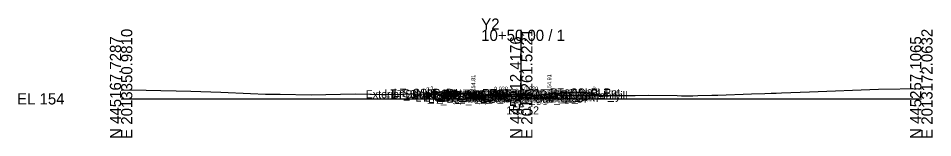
# Model space of a CAD drawing. Extents: x -26 to 203, y -10 to 6017.
# Drawn here: x -25.7 to 202.8, y 990.3 to 1020.1 of the extents above; entities that cross this region are included whole.
import ezdxf

# ---------------------------------------------------------------- set-up
doc = ezdxf.new("R2010")
doc.units = 0
for name, color, linetype in [('Default', 7, 'Continuous'), ('Exist CMT Pavement', 7, 'Continuous'), ('Exist Cross Section Cell', 7, 'Continuous'), ('Exist XS Center Line Elevation Label', 7, 'Continuous'), ('Exist XS Ground Line', 7, 'Continuous'), ('Prop CMT Conc Surface', 7, 'Continuous'), ('Prop CMT Concrete Structures', 7, 'Continuous'), ('Prop CMT Pvmt Course 1', 7, 'Continuous'), ('Prop CMT Pvmt Course 1 CG', 7, 'Continuous'), ('Prop CMT Pvmt Course 2', 7, 'Continuous'), ('Prop CMT Pvmt Course 3', 7, 'Continuous'), ('Prop CMT Pvmt Surface', 7, 'Continuous'), ('Prop CMT Pvmt Wedge Surface 1', 7, 'Continuous'), ('Prop CMT Pvmt Wedge Surface 2', 7, 'Continuous'), ('Prop CMT Pvmt Wedge Surface 3', 7, 'Continuous'), ('Prop CMT Slope Grass', 7, 'Continuous'), ('Prop CMT Subgrade Earthwork', 7, 'Continuous'), ('Prop XS Earthwork Shape', 7, 'Continuous'), ('Prop XS Hydro Elevations', 7, 'Continuous'), ('Prop XS SE Text', 7, 'Continuous'), ('Prop XS Side Slope Text', 7, 'Continuous'), ('Scratch_Level_0', 7, 'Continuous')]:
    doc.layers.add(name, color=color, linetype=linetype)

msp = doc.modelspace()

# ---------------------------------------------------------------- linework, layer by layer
at = {"layer": 'Exist CMT Pavement'}
for points in [[(100, 1001.12), (99.62, 1001.13), (91.64, 1000.99), (91, 1000.98)], [(100, 1001.12), (105, 1001.01)]]:
    msp.add_lwpolyline(points, dxfattribs=at)
at = {"layer": 'Exist Cross Section Cell'}
for p, q in [((100, 1000), (100, 1017.25)), ((0, 1000), (100, 1000)), ((100, 1000), (200, 1000))]:
    msp.add_line(p, q, dxfattribs=at)
at = {"layer": 'Exist XS Ground Line'}
msp.add_lwpolyline([(0, 1002.19), (2.58, 1002.21), (9.96, 1002.11), (13.76, 1002), (17.41, 1001.91), (24.94, 1001.69), (32.32, 1001.34), (36.12, 1001.15), (39.78, 1001.13), (47.51, 1001.03), (58.48, 1001.23), (62.14, 1001.2), (69.66, 1001.12), (70.75, 1001.13), (86.79, 1001.22), (87.86, 1001.19), (89.46, 1000.95), (91.64, 1000.99), (99.62, 1001.13), (100, 1001.12), (106.61, 1000.97), (112.21, 1000.87), (113.83, 1000.85), (118.7, 1000.83), (128.51, 1000.86), (131.77, 1000.91), (139, 1000.8), (140.03, 1000.79), (142.9, 1000.78), (144.16, 1000.81), (147.67, 1000.93), (149.16, 1000.95), (157.51, 1001.24), (160.88, 1001.33), (162.43, 1001.4), (162.94, 1001.43), (163.69, 1001.45), (165.06, 1001.5), (172.01, 1001.76), (189.29, 1002.45), (200, 1002.61)], dxfattribs=at)
at = {"layer": 'Prop CMT Conc Surface'}
for points in [[(88, 1000.81), (88, 1001.31), (87.5, 1001.31)], [(105, 1001.03), (107, 1000.91)], [(107, 1000.91), (107, 1001.41), (107.5, 1001.41)], [(90, 1000.93), (88, 1000.81)]]:
    msp.add_lwpolyline(points, dxfattribs=at)
at = {"layer": 'Prop CMT Concrete Structures'}
for points in [[(90, 1000.93), (88, 1000.81), (88, 1001.31), (87.5, 1001.31)], [(87.5, 1001.31), (87.5, 1000.3), (90, 1000.35)], [(105, 1001.03), (107, 1000.91), (107, 1001.41), (107.5, 1001.41)], [(107.5, 1001.41), (107.5, 1000.4), (105, 1000.45)], [(105, 1000.45), (105, 1001.03)], [(90, 1000.35), (90, 1000.93)]]:
    msp.add_lwpolyline(points, dxfattribs=at)
at = {"layer": 'Prop CMT Pvmt Course 1'}
for points in [[(100, 1001.13), (90, 1000.93)], [(91, 1000.83), (100, 1001.01)], [(100, 1000.88), (100, 1001.13)], [(100, 1001.13), (105, 1001.03)], [(100, 1000.88), (100, 1001.13)], [(100, 1001.01), (100, 1000.88), (100, 1000.88)], [(105, 1000.91), (100, 1001.01)], [(100, 1001.01), (100, 1000.88), (100, 1000.88)], [(105, 1001.03), (105, 1000.78), (105, 1000.78), (105, 1000.91)], [(90, 1000.93), (90, 1000.68)], [(90, 1000.68), (91, 1000.7)], [(91, 1000.7), (91, 1000.83)]]:
    msp.add_lwpolyline(points, dxfattribs=at)
at = {"layer": 'Prop CMT Pvmt Course 1 CG'}
for points in [[(90, 1000.35), (87, 1000.29), (86.66, 999.95)], [(86.66, 999.95), (90, 1000.01)], [(90, 1000.01), (90, 1000.35)], [(105, 1000.45), (108, 1000.39), (108.34, 1000.05)], [(105, 1000.11), (105, 1000.45)], [(108.34, 1000.05), (105, 1000.11)]]:
    msp.add_lwpolyline(points, dxfattribs=at)
at = {"layer": 'Prop CMT Pvmt Course 2'}
for points in [[(91, 1000.7), (90, 1000.68)], [(90, 1000.68), (90, 1000.35)], [(90, 1000.35), (91, 1000.37)], [(91, 1000.37), (91, 1000.7)], [(105, 1000.45), (105, 1000.45), (105, 1000.78), (105, 1000.78)], [(105, 1000.78), (105, 1000.45)]]:
    msp.add_lwpolyline(points, dxfattribs=at)
at = {"layer": 'Prop CMT Pvmt Course 3'}
for points in [[(91, 1000.37), (90, 1000.35)], [(90, 1000.35), (90, 1000.01)], [(90, 1000.01), (91, 1000.03)], [(91, 1000.03), (91, 1000.37)], [(105, 1000.45), (105, 1000.45), (105, 1000.11), (105, 1000.11)], [(105, 1000.11), (105, 1000.45)]]:
    msp.add_lwpolyline(points, dxfattribs=at)
at = {"layer": 'Prop CMT Pvmt Surface'}
for points in [[(100, 1001.13), (90, 1000.93)], [(100, 1001.13), (105, 1001.03)]]:
    msp.add_lwpolyline(points, dxfattribs=at)
at = {"layer": 'Prop CMT Pvmt Wedge Surface 1'}
for points in [[(100, 1001.01), (91, 1000.83)], [(100, 1001.01), (105, 1000.91)], [(105, 1000.78), (105, 1001.03)], [(90, 1000.68), (90, 1000.93)], [(91, 1000.7), (90, 1000.68)], [(91, 1000.83), (91, 1000.7)], [(105, 1000.91), (105, 1000.78), (105, 1000.78)]]:
    msp.add_lwpolyline(points, dxfattribs=at)
at = {"layer": 'Prop CMT Pvmt Wedge Surface 2'}
for points in [[(105, 1000.78), (105, 1001.03)], [(90, 1000.68), (90, 1000.93)], [(100, 1000.88), (90, 1000.68)], [(100, 1000.88), (105, 1000.78)]]:
    msp.add_lwpolyline(points, dxfattribs=at)
at = {"layer": 'Prop CMT Pvmt Wedge Surface 3'}
for points in [[(105, 1000.45), (105, 1001.03)], [(90, 1000.35), (90, 1000.93)], [(100, 1000.55), (90, 1000.35)], [(100, 1000.55), (105, 1000.45)]]:
    msp.add_lwpolyline(points, dxfattribs=at)
at = {"layer": 'Prop CMT Slope Grass'}
for points in [[(87.5, 1001.31), (78, 1001.5), (76.98, 1001.16)], [(107.5, 1001.41), (117, 1001.6), (119.3, 1000.83)]]:
    msp.add_lwpolyline(points, dxfattribs=at)
at = {"layer": 'Prop CMT Subgrade Earthwork'}
for points in [[(90, 1000.01), (86.66, 999.95), (85.25, 1001.36)], [(91, 1000.03), (91.01, 1000.98)], [(105, 1000.11), (104.98, 1001.01)], [(105, 1000.11), (108.34, 1000.05), (109.75, 1001.46)], [(91, 1000.03), (90, 1000.01)], [(105, 1000.11), (105, 1000.11)]]:
    msp.add_lwpolyline(points, dxfattribs=at)
at = {"layer": 'Prop XS Earthwork Shape'}
for points in [[(85.4, 1001.21), (85.25, 1001.36), (78, 1001.5), (76.98, 1001.16)], [(85.4, 1001.21), (85.25, 1001.36), (78, 1001.5), (76.98, 1001.16)], [(85.4, 1001.21), (85.25, 1001.36), (78, 1001.5), (76.98, 1001.16)], [(85.4, 1001.21), (85.25, 1001.36), (78, 1001.5), (76.98, 1001.16)], [(85.4, 1001.21), (86.79, 1001.22), (87.5, 1001.2), (87.5, 1000.3), (90, 1000.35), (90, 1000.93), (91.01, 1000.95), (91, 1000.03), (90, 1000.01), (86.66, 999.95)], [(85.4, 1001.21), (86.79, 1001.22), (87.5, 1001.2), (87.5, 1000.3), (90, 1000.35), (90, 1000.93), (91.01, 1000.95), (91, 1000.03), (90, 1000.01), (86.66, 999.95)], [(85.4, 1001.21), (86.79, 1001.22), (87.5, 1001.2), (87.5, 1000.3), (90, 1000.35), (90, 1000.93), (91.01, 1000.95), (91, 1000.03), (90, 1000.01), (86.66, 999.95)], [(85.4, 1001.21), (86.79, 1001.22), (87.5, 1001.2), (87.5, 1000.3), (90, 1000.35), (90, 1000.93), (91.01, 1000.95), (91, 1000.03), (90, 1000.01), (86.66, 999.95)], [(90, 1000.93), (88, 1000.81), (88, 1001.17), (87.86, 1001.19), (87.5, 1001.2), (87.5, 1000.3), (90, 1000.35)], [(88, 1000.81), (88, 1001.17), (87.86, 1001.19), (87.5, 1001.2), (87.5, 1000.3), (90, 1000.35), (90, 1000.93)], [(90, 1000.93), (88, 1000.81), (88, 1001.17), (87.86, 1001.19), (87.5, 1001.2), (87.5, 1000.3), (90, 1000.35)], [(87.5, 1001.2), (87.5, 1000.3), (90, 1000.35), (90, 1000.93), (88, 1000.81), (88, 1001.17), (87.86, 1001.19)], [(90, 1000.93), (88, 1000.81), (88, 1001.17), (89.46, 1000.95), (91, 1000.98), (91.01, 1000.98), (91.01, 1000.95)], [(88, 1000.81), (88, 1001.17), (89.46, 1000.95), (91, 1000.98), (91.01, 1000.98), (91.01, 1000.95), (90, 1000.93)], [(90, 1000.93), (88, 1000.81), (88, 1001.17), (89.46, 1000.95), (91, 1000.98), (91.01, 1000.98), (91.01, 1000.95)], [(90, 1000.93), (88, 1000.81), (88, 1001.17), (89.46, 1000.95), (91, 1000.98), (91.01, 1000.98), (91.01, 1000.95)], [(91.64, 1000.99), (91.01, 1000.98), (91.01, 1000.95), (99.76, 1001.13), (99.62, 1001.13)], [(91.64, 1000.99), (91.01, 1000.98), (91.01, 1000.95), (99.76, 1001.13), (99.62, 1001.13)], [(91.64, 1000.99), (91.01, 1000.98), (91.01, 1000.95), (99.76, 1001.13), (99.62, 1001.13)], [(91.64, 1000.99), (91.01, 1000.98), (91.01, 1000.95), (99.76, 1001.13), (99.62, 1001.13)], [(105, 1000.45), (105, 1001.01), (105.56, 1001), (107, 1000.91), (107, 1000.97), (107.5, 1000.96), (107.5, 1000.4)], [(105, 1000.45), (105, 1001.01), (105.56, 1001), (107, 1000.91), (107, 1000.97), (107.5, 1000.96), (107.5, 1000.4)], [(105, 1000.45), (105, 1001.01), (105.56, 1001), (107, 1000.91), (107, 1000.97), (107.5, 1000.96), (107.5, 1000.4)], [(107, 1000.91), (107, 1000.97), (107.5, 1000.96), (107.5, 1000.4), (105, 1000.45), (105, 1001.01), (105.56, 1001)], [(107, 1000.91), (107, 1000.97), (106.61, 1000.97), (105.56, 1001)], [(105.56, 1001), (106.61, 1000.97), (107, 1000.97), (107, 1000.91)], [(107, 1000.91), (107, 1000.97), (106.61, 1000.97), (105.56, 1001)], [(107, 1000.91), (107, 1000.97), (106.61, 1000.97), (105.56, 1001)], [(109.22, 1000.92), (109.75, 1001.46), (117, 1001.6), (119.3, 1000.83), (118.7, 1000.83), (113.83, 1000.85), (112.21, 1000.87)], [(109.22, 1000.92), (109.75, 1001.46), (117, 1001.6), (119.3, 1000.83), (118.7, 1000.83), (113.83, 1000.85), (112.21, 1000.87)], [(109.22, 1000.92), (109.75, 1001.46), (117, 1001.6), (119.3, 1000.83), (118.7, 1000.83), (113.83, 1000.85), (112.21, 1000.87)], [(109.22, 1000.92), (109.75, 1001.46), (117, 1001.6), (119.3, 1000.83), (118.7, 1000.83), (113.83, 1000.85), (112.21, 1000.87)], [(105, 1000.11), (105, 1000.45), (107.5, 1000.4), (107.5, 1000.96), (109.22, 1000.92), (108.34, 1000.05)], [(105, 1000.11), (105, 1000.45), (107.5, 1000.4), (107.5, 1000.96), (109.22, 1000.92), (108.34, 1000.05)], [(105, 1000.11), (105, 1000.45), (107.5, 1000.4), (107.5, 1000.96), (109.22, 1000.92), (108.34, 1000.05)], [(105, 1000.11), (105, 1000.45), (107.5, 1000.4), (107.5, 1000.96), (109.22, 1000.92), (108.34, 1000.05)]]:
    msp.add_lwpolyline(points, close=True, dxfattribs=at)

# ---------------------------------------------------------------- texts
at = {"layer": 'Default'}
msp.add_text('-', height=0.0001, dxfattribs=at).set_placement((0, 1000))
at = {"layer": 'Exist Cross Section Cell'}
for s, p in [('Y2', (90, 1017.25)), ('10+50.00 / 1', (90, 1014.45)), ('EL 154', (-26, 998.6))]:
    msp.add_text(s, height=2.8, dxfattribs=at).set_placement(p)
for s, p in [('E 2013350.9810', (2.8, 990)), ('E 2013261.5221', (102.8, 990)), ('E 2013172.0632', (202.8, 990)), ('N 445167.7287', (0, 990)), ('N 445212.4176', (100, 990)), ('N 445257.1065', (200, 990))]:
    msp.add_text(s, height=2.8, rotation=90, dxfattribs=at).set_placement(p)
at = {"layer": 'Exist XS Center Line Elevation Label'}
msp.add_text('155.12', height=2, dxfattribs=at).set_placement((96.27, 996.12))
at = {"layer": 'Prop XS Hydro Elevations'}
for s, p in [('154.81', (88.5, 1001.81)), ('154.91', (107.5, 1001.91))]:
    msp.add_text(s, height=1, rotation=90, dxfattribs=at).set_placement(p)
at = {"layer": 'Prop XS SE Text'}
for rotation, p in [(1.1458, (93.23, 1002)), (358.8542, (100.77, 1002.12))]:
    msp.add_text('0.020', height=1, rotation=rotation, dxfattribs=at).set_placement(p)
at = {"layer": 'Prop XS Side Slope Text'}
for rotation, p in [(18.4332, (76.5, 1001.79)), (341.5668, (117.64, 1002.18))]:
    msp.add_text('3:1', height=1, rotation=rotation, dxfattribs=at).set_placement(p)
at = {"layer": 'Scratch_Level_0'}
for s, p in [('Exterior Boundary', (61.12, 1000.16)), ('LT_Sub_Trench_Out_DLT', (65.82, 1000.36)), ('LT_Slope_Fill', (67.5, 1000.16)), ('LT_CSLP_Pnt', (68.17, 1000.5)), ('LT_CG1_Shelf_Out', (73.55, 999.29)), ('LT_CG_Top_Face', (75.26, 1000.31)), ('LT_CG_Top_BOC', (75.78, 1000.31)), ('LT_CG_Bot_BOC', (75.81, 999.3)), ('LT_PV_Sub_Tie_Out', (75.96, 999.98)), ('LT_CG_Top_Gut', (76.24, 999.81)), ('LT_Sub_OEOP', (76.77, 998.95)), ('LT_PV_OEEOP_EG', (78.54, 999.98)), ('LT_CG_Bot_IE', (79.91, 999.35)), ('LT_Sub_OEOT', (80.08, 999.01)), ('LT_PV2_OEOT', (80.17, 999.68)), ('LT_PV3_OEOT', (80.17, 999.35)), ('LT_Sub_OEEOP', (80.21, 999.03)), ('LT_PV2_OEEOP', (80.31, 999.7)), ('LT_PV3_OEEOP', (80.31, 999.37)), ('LT_PV1_OEOT', (80.74, 999.93)), ('LT_PV1_OEEOP', (80.87, 999.83)), ('RT_PV_IEEOP_EG', (88.14, 1000.12)), ('LT_PV_IEEOP_EG', (88.19, 1000.12)), ('RT_PV_Sub_Tie_Out', (89.88, 1000.01)), ('RT_PV2_IEEOP', (89.91, 999.88)), ('RT_PV3_IEEOP', (89.91, 999.55)), ('LT_PV2_IEEOP', (89.95, 999.88)), ('LT_PV3_IEEOP', (89.95, 999.55)), ('RT_Sub_Trench_Out_DLT', (90.27, 1000.46)), ('RT_PV1_IEEOP', (90.47, 1000.01)), ('LT_PV1_IEEOP', (90.52, 1000.01)), ('RT_PV_OEEOP_EG', (92.5, 1000.01)), ('PV2_PGL', (93.91, 999.88)), ('RT_Sub_OEEOP', (94.17, 999.11)), ('RT_CG_Top_Face', (94.21, 1000.41)), ('RT_PV2_OEEOP', (94.26, 999.78)), ('RT_PV3_OEEOP', (94.26, 999.45)), ('PV1_PGL', (94.47, 1000.13)), ('RT_CG1_Shelf_Out', (94.5, 999.39)), ('RT_PV1_OEEOP', (94.83, 999.91)), ('RT_CG_Bot_IE', (94.87, 999.45)), ('RT_Sub_OEOT', (95.03, 999.11)), ('RT_PV2_OEOT', (95.13, 999.78)), ('RT_PV3_OEOT', (95.13, 999.45)), ('RT_CG_Top_Gut', (95.19, 999.91)), ('RT_PV1_OEOT', (95.69, 1000.03)), ('RT_CG_Top_BOC', (95.74, 1000.41)), ('RT_CG_Bot_BOC', (95.77, 999.4)), ('RT_Sub_OEOP', (98.4, 999.05)), ('Exterior Boundary', (103.44, 999.83)), ('RT_CSLP_Pnt', (107.13, 1000.6)), ('RT_Slope_Fill', (109.77, 999.83))]:
    msp.add_text(s, height=2, dxfattribs=at).set_placement(p)

doc.saveas('drawing.dxf')
